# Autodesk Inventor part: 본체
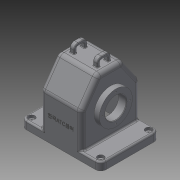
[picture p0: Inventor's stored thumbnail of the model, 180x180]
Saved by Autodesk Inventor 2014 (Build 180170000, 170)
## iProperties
Created: 2016-12
Part Number: 본체
Material: 일반
Document SubType Name: Modeling
Designer: NET
Density: 1 g/cm^3
Appearance: 기본값
Author: NET
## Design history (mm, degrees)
sketch "스케치1"
  geometry: L1 (0, 0)-(150, 0); L2 (150, 0)-(150, 15); L3 (150, 15)-(113.5, 15); L4 (113.5, 15)-(113.5, 125); L5 (113.5, 125)-(36.5, 125); L6 (36.5, 125)-(36.5, 15); L7 (36.5, 15)-(0, 15); L8 (0, 15)-(0, 0)
  constraints: 16 end point, 6 parallel, 2 equal length, 1 horizontal, 1 perpendicular
  dimensions: "d0" = 150 distance of L1.start L1.end; "d1" = 77 distance between parallel lines of L4 L6; "d2" = 125 distance between parallel lines of L1 L5; "d3" = 15 distance of L7.end L1.start
extrude "돌출1" new body sketch "스케치1" stored distance "d5" = 110; taper "d6" = 0 deg
sketch "스케치2"
  geometry: L1 (110, 110)-(0, 110) reference; L2 (0, 0)-(0, 110) reference; L3 (110, 110)-(110, 0) reference; L4 (0, 65)-(110, 65); L5 (110, 0)-(0, 0) reference; L6 (0, -15)-(0, 0) reference; L7 (110, -15)-(0, -15) reference; L8 (110, 0)-(110, -15) reference; L9 (0, 65)-(31.509, 110); L10 (110, 65)-(78.491, 110); L11 (0, 65)-(0, 110); L12 (0, 110)-(31.509, 110); L13 (78.491, 110)-(110, 110); L14 (110, 110)-(110, 65); 1 further point
  constraints: 14 end point, 4 collinear, 4 point on line, 1 equal length, 1 perpendicular
  dimensions: "d7" = 80 distance between parallel lines of L7 L4; "d8" = 35 deg angle of L2 L9
extrude "돌출2" cut sketch "스케치2" stored distance "d9" = 110; taper "d10" = 0 deg
node "작업 평면2"
sketch "스케치4"
  geometry: L1 (78.491, 110)-(110, 65) reference; L2 (110, 0)-(110, 65) reference; L3 (110, 0)-(0, 0) reference; L4 (0, 65)-(0, 0) reference; L5 (0, 65)-(31.509, 110) reference; L6 (78.491, 110)-(31.509, 110) reference; L7 (0, -15)-(110, -15) reference; L8 (0, 0)-(0, -15) reference; L9 (110, 0)-(0, 0) reference; L10 (110, -15)-(110, 0) reference; L11 (5, 63.424)-(34.112, 105); L12 (34.112, 105)-(75.888, 105); L13 (75.888, 105)-(105, 63.424); L14 (105, 63.424)-(105, -15); L15 (5, 63.424)-(5, -15); 1 further point
  constraints: 10 end point, 3 perpendicular, 2 parallel, 2 point on line
  dimensions: "d14" = 5 distance between parallel lines of L15 L4; "d15" = 5 distance between parallel lines of L2 L14; "d17" = 5 distance between parallel lines of L12 L6; "d18" = 5 distance between parallel lines of L11 L5; "d19" = 5 distance between parallel lines of L13 L1
extrude "돌출3" cut sketch "스케치4" stored distance "d20" = 67; taper "d21" = 0 deg
node "작업 평면3"
node "작업 평면4"
sketch "스케치5"
  geometry: L1 (0, 0)-(0, 65) reference; L2 (110, 65)-(110, 0) reference; L3 (31.509, 110)-(78.491, 110) reference; L4 (110, -15)-(0, -15) reference; L5 (0, 50)-(110, 50); L6 (55, -15)-(55, 110); C1 r 37.5 at (55, 50); 1 further point
  constraints: 4 end point, 3 point on line, 2 midpoint, 1 centre point, 1 coincident, 1 parallel
  dimensions: "d22" = 65 distance between parallel lines of L4 L5; "d23" = 75 diameter of C1
extrude "돌출4" join sketch "스케치5" distance "d24" = 5; taper "d25" = 0 deg
sketch "스케치7"
  geometry: C1 r 37.5 at (0, 0) reference; C2 r 20 at (0, 0); 1 further point
  constraints: 1 centre point, 1 coincident
  dimensions: "d26" = 40 diameter of C2
sketch "스케치6"
  geometry: L1 (5, -15)-(5, 63.424) reference; L2 (105, -15)-(5, -15) reference; L3 (105, 63.424)-(105, -15) reference; L4 (75.888, 105)-(105, 63.424) reference; L5 (34.112, 105)-(75.888, 105) reference; L6 (5, 63.424)-(34.112, 105) reference; C1 r 20 at (55, 50) reference; C2 r 27 at (55, 50); 1 further point
  constraints: 1 centre point, 1 coincident
  dimensions: "d27" = 54 diameter of C2
sketch "스케치8"
  geometry: L1 (31.5, 102.5)-(31.5, 27.5) reference; L2 (31.5, 65)-(55.5, 65); L3 (55.5, 92)-(41.5, 106); L4 (41.5, 106)-(41.5, 65); L5 (55.5, 92)-(55.5, 65); L6 (41.5, 65)-(55.5, 65); 1 further point
  constraints: 10 end point, 2 perpendicular, 1 collinear, 1 midpoint, 1 parallel, 1 point on line
  dimensions: "d31" = 54 diameter of L3.start L2; "d32" = 45 deg angle of L5 L3; "d33" = 24 distance between parallel lines of L1 L5; "d34" = 14 distance between parallel lines of L5 L4
revolve "회전1" sketch "스케치8" stored, may be unused: angle "d35" = 90 deg
sketch "스케치9"
  geometry: C1 r 37.5 at (55, 50) reference; C2 r 37.5 at (55, 50) reference; C3 r 31 at (55, 50); 1 further point
  constraints: 1 centre point, 1 coincident
  dimensions: "d36" = 62 diameter of C3
extrude "돌출5" join sketch "스케치9" distance "d37" = 10; taper "d38" = 0 deg
extrude "돌출6" cut sketch "스케치7" stored distance "d39" = 10; taper "d40" = 0 deg
sketch "스케치10"
  geometry: L1 (77, 0)-(0, 0) reference; L2 (0, 0)-(0, -46.981) reference; L3 (0, -46.981)-(77, -46.981) reference; L4 (77, 0)-(77, -46.981) reference; L5 (0, -23.491)-(77, -23.491); L6 (38.5, 0)-(38.5, -46.981); L7 (56.5, -10.991)-(56.5, -35.991); L8 (20.5, -10.991)-(20.5, -35.991); L9 (64.5, -35.991)-(64.5, -10.991); L10 (12.5, -10.991)-(12.5, -35.991); L11 (12.5, -10.991)-(20.5, -10.991); L12 (12.5, -35.991)-(20.5, -35.991); L13 (56.5, -10.991)-(64.5, -10.991); L14 (56.5, -35.991)-(64.5, -35.991); 7 further points
  constraints: 20 end point, 10 midpoint, 10 parallel, 4 horizontal alignment, 1 perpendicular
  dimensions: "d44" = 36 distance between parallel lines of L7 L8; "d45" = 18 distance between parallel lines of L7 L6; "d46" = 52 distance between parallel lines of L9 L10; "d47" = 26 distance between parallel lines of L9 L6; "d48" = 25 distance of L10.start L10.end
extrude "돌출7" join sketch "스케치10" distance "d49" = 15; taper "d50" = 0 deg
sketch "스케치11"
  geometry: L1 (25, 0)-(25, 15) reference; L2 (0, 15)-(25, 15) reference; L3 (35.991, 0)-(-10.991, 0) reference; L4 (5, 0)-(20, 0); L5 (20, 0)-(20, 10); L6 (20, 10)-(5, 10); L7 (5, 10)-(5, 0); 1 further point
  constraints: 8 end point, 2 parallel, 1 horizontal, 1 perpendicular, 1 point on line
  dimensions: "d51" = 5 distance between parallel lines of L6 L2; "d52" = 15 distance of L5.end L6.end; "d53" = 5 distance between parallel lines of L1 L5
extrude "돌출8" cut sketch "스케치11" stored distance "d54" = 15; taper "d55" = 0 deg
fillet "모깎기1" dims "d56" = 10
sketch "스케치13"
  geometry: A1 r 10 centre (-26.5, 100) between (-26.5, 110) and (-36.5, 100) reference; A2 r 10 centre (-26.5, 10) between (-36.5, 10) and (-26.5, 0) reference; 3 further points
  constraints: 2 coincident
hole "구멍1" sketch "스케치13" at (-26.5, 100), (-26.5, 10) diameter "d57" = 5; stored, may be unused: countersink angle "d61" = 90 deg, drill point angle "d63" = 118 deg; dims "d58" = 6, "d59" = 12, "d60" = 5, "d62" = 8
sketch "스케치14"
  geometry: C1 r 20 at (0, 0) reference; 2 further points
  constraints: 1 vertical alignment
  dimensions: "d64" = 29 distance of C1.centre point (0, 29)
hole "구멍2" sketch "스케치14" at (0, 29) diameter "d65" = 2.459; stored, may be unused: countersink angle "d69" = 90 deg, drill point angle "d71" = 118 deg; dims "d66" = 6, "d67" = 12, "d68" = 5, "d70" = 8
sketch "스케치15"
  geometry: C1 r 20 at (0, 0) reference; 2 further points
  constraints: 1 vertical alignment
  dimensions: "d75" = 26 distance of C1.centre point (0, 26)
hole "구멍3" sketch "스케치15" at (0, 26) diameter "d76" = 2.459; stored, may be unused: countersink angle "d80" = 90 deg, drill point angle "d82" = 118 deg; dims "d77" = 6, "d78" = 12, "d79" = 5, "d81" = 8
sketch "스케치16"
  geometry: L1 (10, 0)-(140, 0) reference; L2 (36.5, 80)-(36.5, 15) reference; 2 further points
  constraints: 1 other
  dimensions: "d86" = 38.5 distance from line of point (75, 45) L2; "d87" = 45 distance from line of point (75, 45) L1
feature "엠보싱1" sketch "스케치16" dims "d0" = 150, "d1" = 77, "d2" = 125, "d3" = 15, "d88" = 0.5, "d89" = 0
fillet "모깎기2" dims "d90" = 10
fillet "모깎기3" dims "d91" = 10
fillet "모깎기4" dims "d92" = 8
fillet "모깎기5" dims "d93" = 8
chamfer "모따기1" distance "d94" = 1; stored, may be unused: second distance "d95" = 2, angle "d96" = 45 deg
chamfer "모따기2" distance "d97" = 1; stored, may be unused: second distance "d98" = 2, angle "d99" = 45 deg
fillet "모깎기6" dims "d100" = 3
fillet "모깎기7" dims "d101" = 3
fillet "모깎기8" dims "d102" = 1
fillet "모깎기9" dims "d103" = 3
fillet "모깎기10" dims "d104" = 3
fillet "모깎기11" dims "d105" = 3
fillet "모깎기12" dims "d106" = 1
node "솔리드1"
mirror "대칭1"
pattern_circular "원형 패턴1" dims angle "d73" = 360 deg
pattern_circular "원형 패턴2" dims angle "d84" = 360 deg
node "투영된 루프1"
node "투영된 루프2"
node "투영된 루프3"
node "투영된 루프4"
